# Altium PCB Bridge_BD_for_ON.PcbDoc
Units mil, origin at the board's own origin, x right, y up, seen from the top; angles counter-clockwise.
Board outline 3500 x 4000 mil, 2 copper layers (Top Layer, Bottom Layer); 143 components, 90 nets, 417 pads, 92 vias.
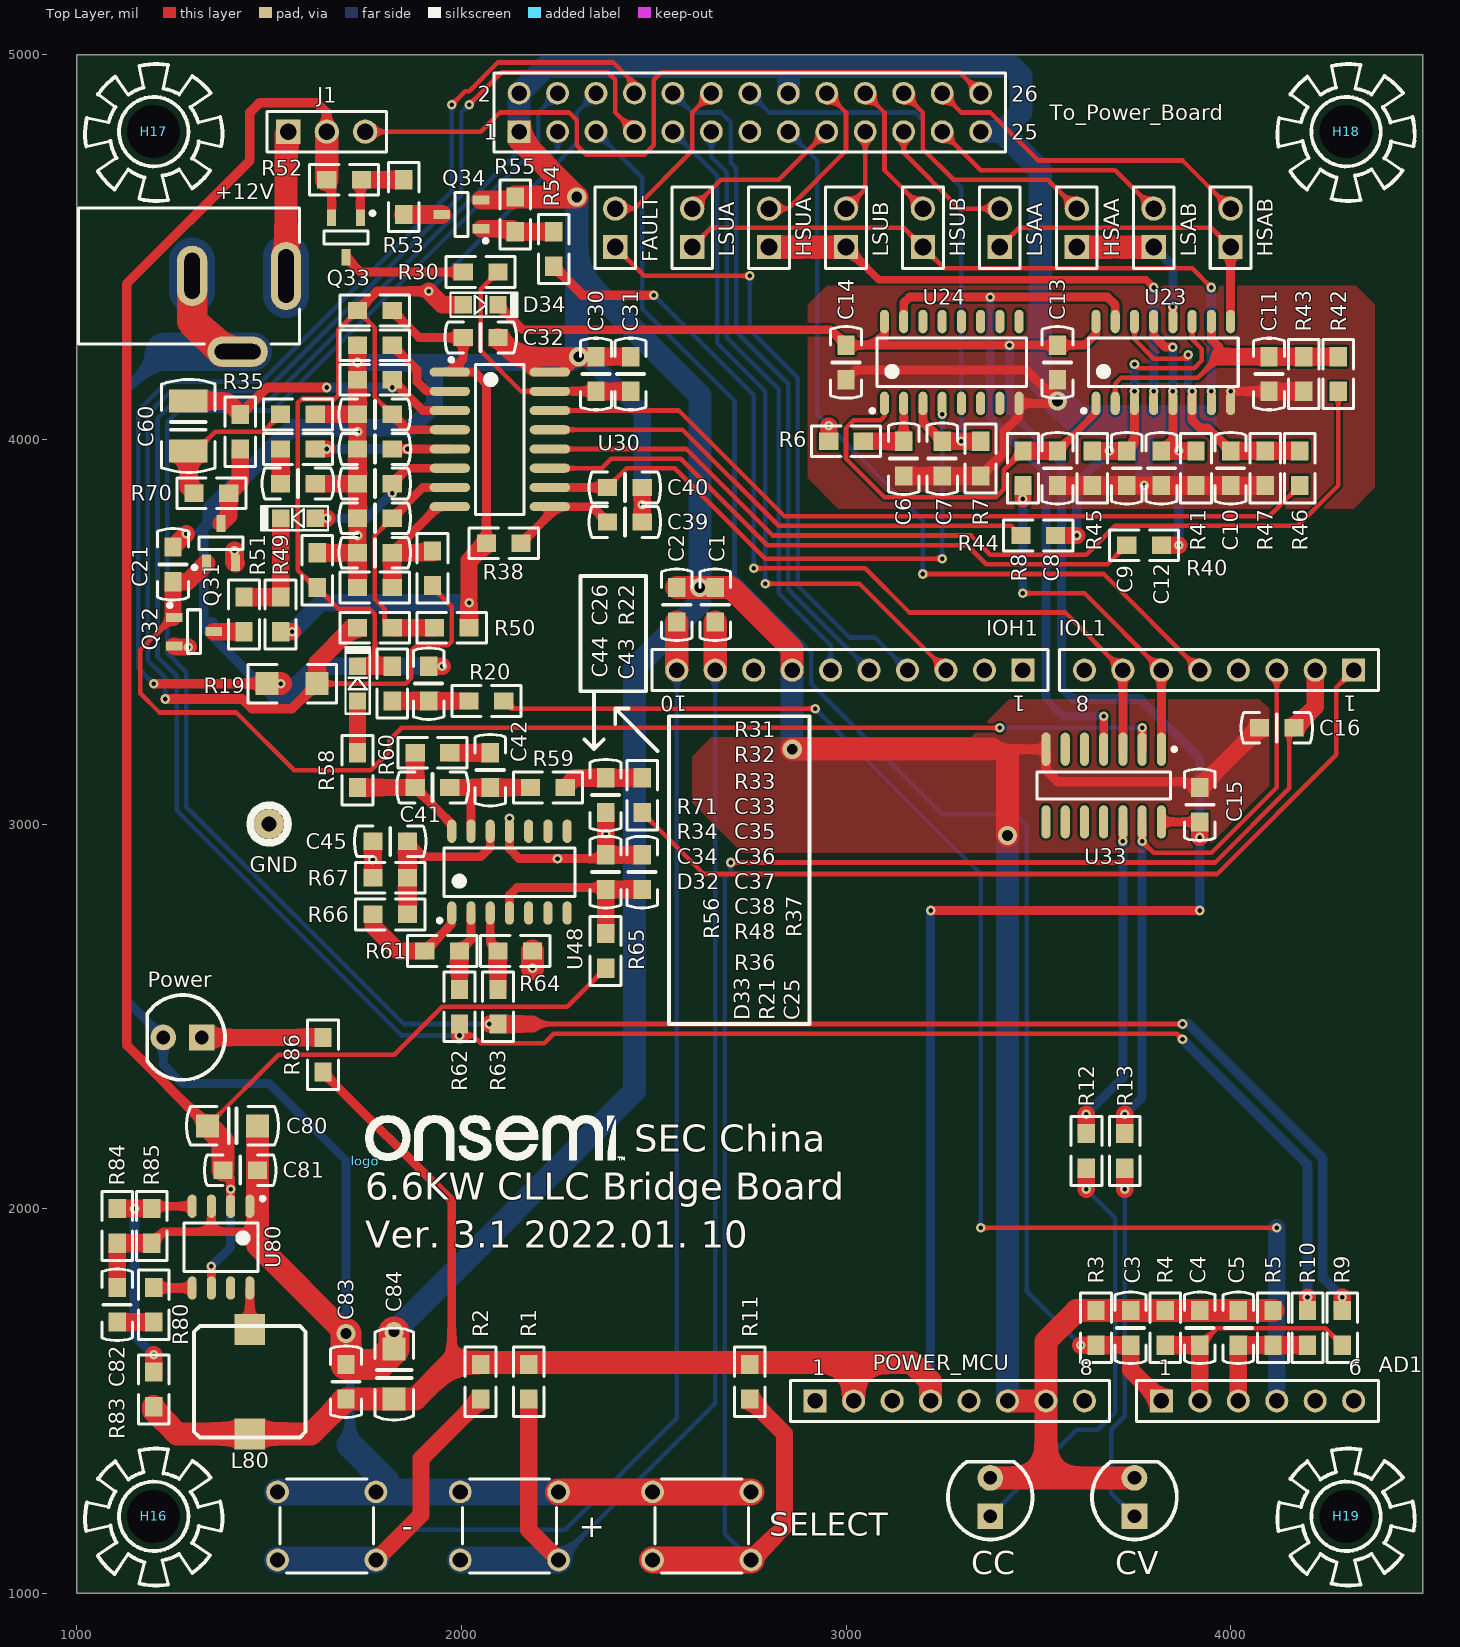
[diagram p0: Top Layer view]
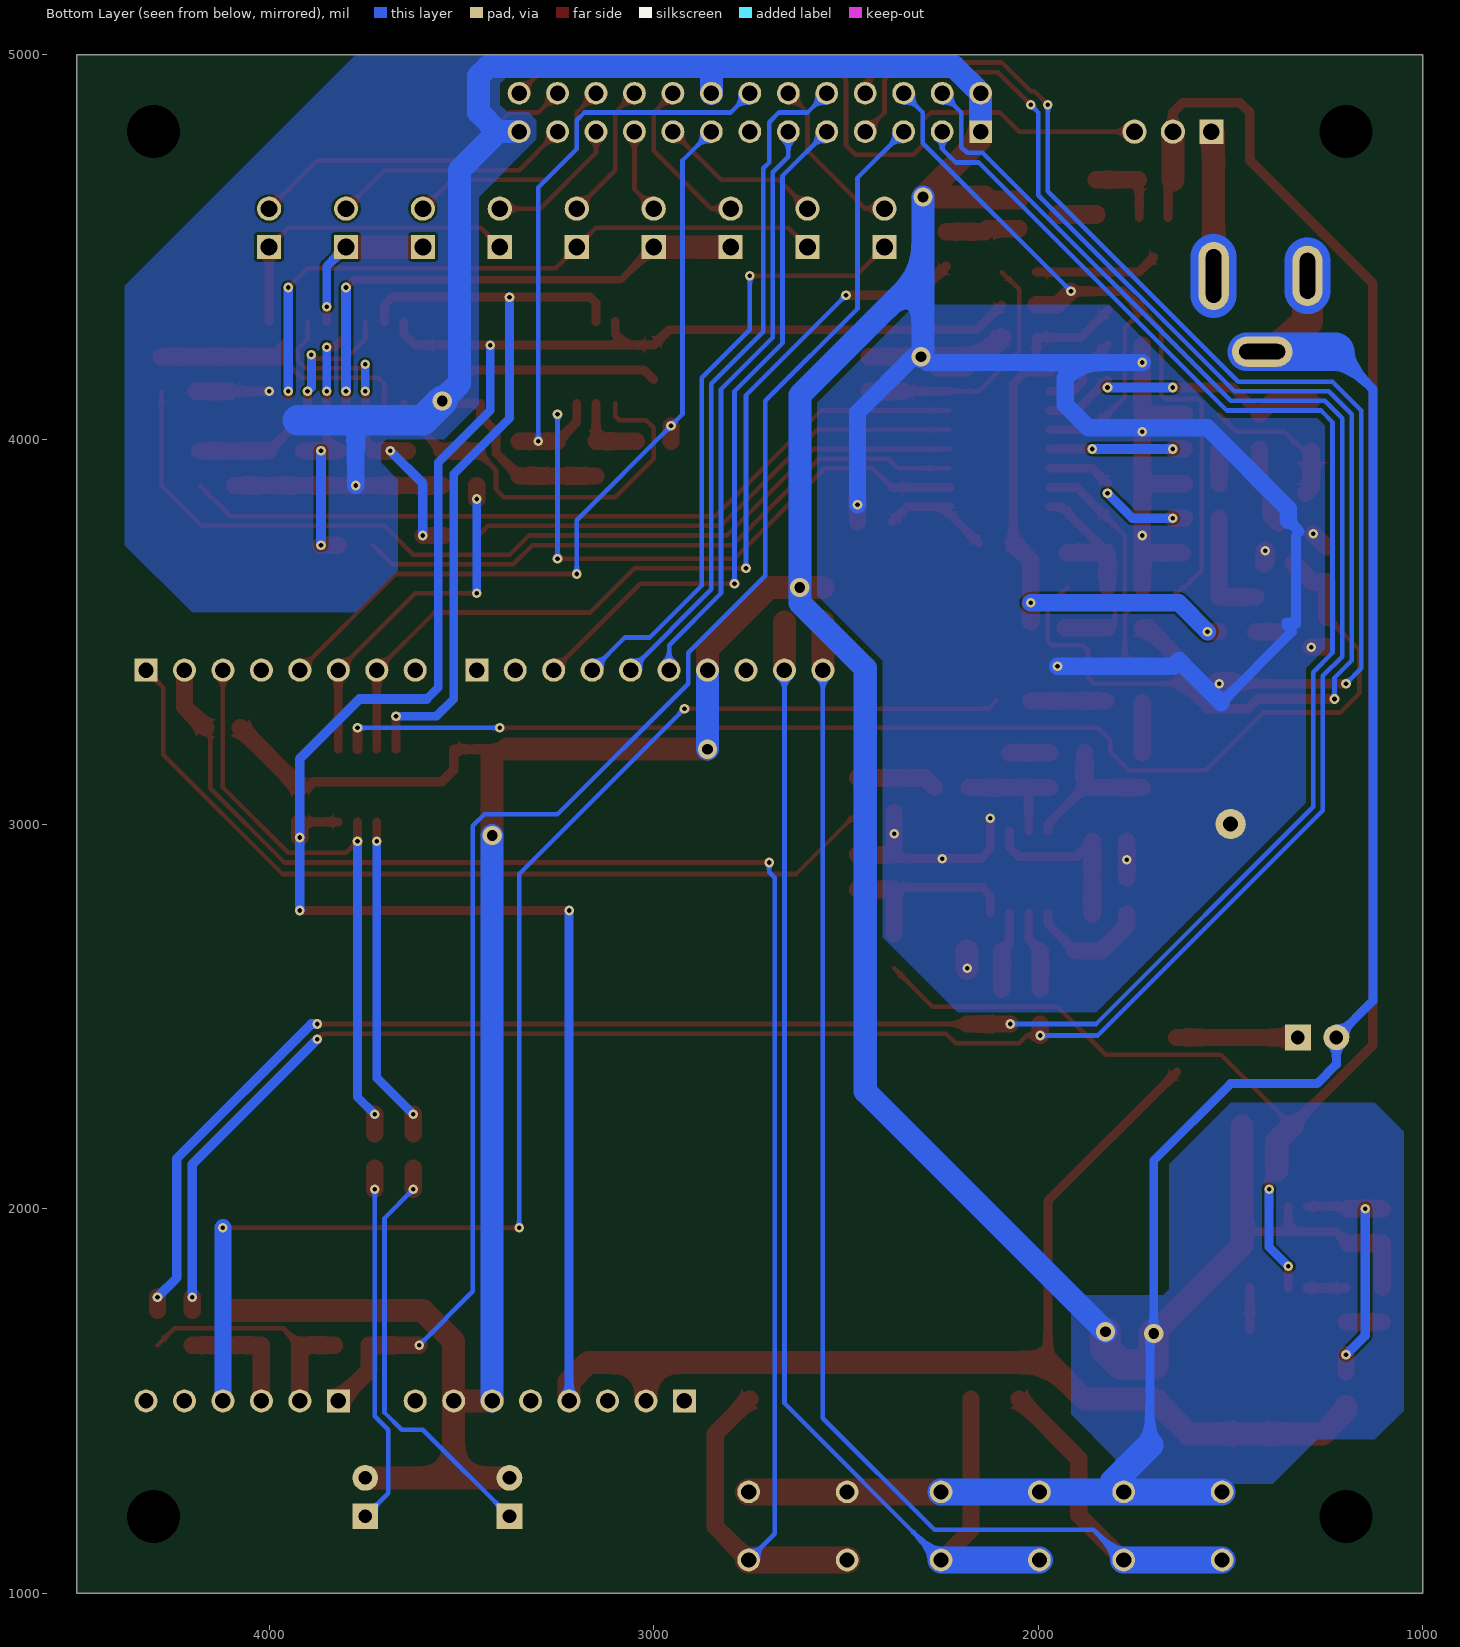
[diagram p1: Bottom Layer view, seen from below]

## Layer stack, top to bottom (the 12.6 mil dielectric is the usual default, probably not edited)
Top Solder: solder mask 0.4, Solder Resist, Dk 3.5
Top Layer: signal copper 1.4
Dielectric 1: dielectric 12.6, FR-4, Dk 4.8
Bottom Layer: signal copper 1.4
Bottom Solder: solder mask 0.4, Solder Resist, Dk 3.5

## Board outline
1000,1000 1000,5000 4500,5000 4500,1000

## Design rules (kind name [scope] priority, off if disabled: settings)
Clearance [All] p1: gap=6 ignorepadtopadclearanceinfootprint=FALSE
PolygonConnect [All] p1: connectstyle=Direct reliefconductorwidth=10 reliefentries=4 polygonreliefangle="90 Angle" airgapwidth=10
RoutingVias [All] p1: holewidth=28 width=50 viastyle="Through Hole" minholewidth=28 minwidth=50 maxholewidth=28 maxwidth=50
SolderMaskExpansion [All] p1: expansion=4
Width [All] p1: maxlimit=200 minlimit=10 preferedwidth=23
30 further rules are at their usual default settings.

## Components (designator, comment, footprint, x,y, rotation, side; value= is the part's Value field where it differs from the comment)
+ "430156050726" 4301x60507x6 2125,1175 r180 top
+12V "PWR2.5" KLD-0202 1004.72,4425 r0 top locked
- "430156050726" 4301x60507x6 1650,1175 r180 top
AD1 "61300611821" 61300611821 4070,1500 r0 top locked
C1 "102" SMT_0805_CM 2660,3570 r270 top
C2 "102" SMT_0805_CM 2560,3570 r270 top
C3 "101" SMT_0805_CM 3740,1690 r270 top
C4 "101" SMT_0805_CM 3920,1690 r270 top
C5 "101" SMT_0805_CM 4020,1690 r270 top
C6 "10" SMT_0805_CM 3150,3950 r90 top
C7 "10" SMT_0805_CM 3250,3950 r90 top
C8 "104" SMT_0805_CM 3550,3925 r90 top
C9 "101" SMT_0805_CM 3730,3925 r90 top
C10 "101" SMT_0805_CM 4000,3925 r90 top
C11 "101" SMT_0805_CM 4100,4170 r90 top
C12 "101" SMT_0805_CM 3820,3925 r90 top
C13 "104" SMT_0805_CM 3550,4200 r90 top
C14 "104" SMT_0805_CM 3000,4200 r90 top
C15 "104" SMT_0805_CM 3920,3050 r270 top
C16 "102" SMT_0805_CM 4120,3250 r0 top
C21 "101" SMT_0805_CM 1250,3675 r270 top
C25 "225" SMT_0805_CM 1915,3365 r270 top
C26 "225" SMT_0805_CM 2375,3075 r90 top
C30 "104" SMT_0805_CM 2350,4170 r270 top
C31 "225" SMT_0805_CM 2440,4170 r270 top
C32 "104" SMT_0805_CM 2050,4265 r180 top
C33 "471" SMT_0805_CM 1775,4065 r0 top
C34 "223" SMT_0805_CM 1575,3885 r180 top
C35 "222" SMT_0805_CM 1775,3975 r0 top
C36 "105" SMT_0805_CM 1775,3885 r0 top
C37 "471" SMT_0805_CM 1775,3795 r0 top
C38 "10" SMT_0805_CM 1775,3705 r0 top
C39 "471" SMT_0805_CM 2425,3785 r180 top
C40 "NC" SMT_0805_CM 2425,3875 r180 top
C41 "104" SMT_0805_CM 1925,3095 r0 top
C42 "NC" SMT_0805_CM 2075,3140 r270 top
C43 "225" SMT_0805_CM 2470,2875 r270 top
C44 "104" SMT_0805_CM 2375,2875 r270 top
C45 "102" SMT_0805_CM 1815,2955 r0 top
C60 "226" SMT_1210 1290,4035 r270 top
C80 "106/25V" SMT_1206_CM 1405,2215 r180 top
C81 "104" SMT_0805_CM 1425,2100 r180 top
C82 "103" SMT_0805_CM 1105,1750 r90 top
C83 "104" SMT_0805_CM 1700,1550 r270 top
C84 "106/25V" SMT_1206_CM 1825,1570 r270 top
CC "Green" "LED 5MM-R" 3375,1250 r90 top
CV "Green" "LED 5MM-R" 3750,1250 r90 top
D32 "BAS16H" SOD-323M 1620,3795 r180 top
D33 "BAS16H" SOD-323M 1730,3320 r90 top
D34 "BAS16H" SOD-323M 2005,4350 r0 top
FAULT "61300211121" 61300211121 2400,4550 r90 top
GND "" test 1500,3000 r0 top
H16 "Comment" HOLE3.5-2 1200,1200 r0 top locked
H17 "Comment" HOLE3.5-2 1200,4800 r0 top locked
H18 "Comment" HOLE3.5-2 4300,4800 r0 top locked
H19 "Comment" HOLE3.5-2 4300,1200 r0 top locked
HSAA "61300211121" 61300211121 3600,4550 r90 top
HSAB "61300211121" 61300211121 4000,4550 r90 top
HSUA "61300211121" 61300211121 2800,4550 r90 top
HSUB "61300211121" 61300211121 3200,4550 r90 top
IOH1 "61301011821" 61301011821 3010,3400 r180 top locked
IOL1 "61300811821" 61300811821 3970,3400 r180 top locked
J1 "61300311121" 61300311121 1650,4800 r0 top
L80 "22uH" INDUCTOR-7*7*3.5 1450,1550 r270 top
logo "Comment" Logo_S 1750,2125 r0 top
LSAA "61300211121" 61300211121 3400,4550 r90 top
LSAB "61300211121" 61300211121 3800,4550 r90 top
LSUA "61300211121" 61300211121 2600,4550 r90 top
LSUB "61300211121" 61300211121 3000,4550 r90 top
Power "Green" "LED 5MM-R" 1275,2445 r180 top locked
POWER_MCU "61300811821" 61300811821 3270,1500 r0 top locked
Q31 "2V7002LT1G" SOT-23-3L 1375,3730 r90 top
Q32 "2V7002LT1G" SOT-23-3L 1305,3500 r0 top
Q33 "NSV40200LT1G" SOT-23-3L 1700,4525 r270 top
Q34 "MMBT3904LT1G" SOT-23-3L 2000,4585 r180 top
R1 "2.2K" SMT_0805_RM 2175,1550 r270 top
R2 "2.2K" SMT_0805_RM 2050,1550 r270 top
R3 "20K" SMT_0805_RM 3650,1690 r90 top
R4 "4.75K" SMT_0805_RM 3830,1690 r90 top
R5 "4.75K" SMT_0805_RM 4110,1690 r90 top
R6 "100" SMT_0805_RM 3000,3995 r0 top
R7 "6.2K" SMT_0805_RM 3350,3950 r270 top
R8 "100" SMT_0805_RM 3460,3925 r90 top
R9 "12.7K" SMT_0805_RM 4290,1690 r90 top
R10 "12.7K" SMT_0805_RM 4200,1690 r90 top
R11 "2.2K" SMT_0805_RM 2750,1550 r270 top
R12 "220" SMT_0805_RM 3625,2150 r270 top
R13 "220" SMT_0805_RM 3725,2150 r270 top
R19 "100" SMT_1206_RM 1560,3365 r0 top
R20 "1K" SMT_0805_RM 2065,3320 r180 top
R21 "120K" SMT_0805_RM 1820,3365 r90 top
R22 "1K" SMT_0805_RM 2470,3075 r90 top
R30 "10" SMT_0805_RM 2050,4435 r0 top
R31 "1M" SMT_0805_RM 1775,4335 r180 top
R32 "51K" SMT_0805_RM 1775,4245 r180 top
R33 "10K" SMT_0805_RM 1775,4155 r180 top
R34 "20K" SMT_0805_RM 1575,3975 r180 top
R35 "24K" SMT_0805_RM 1425,4020 r270 top
R36 "20K" SMT_0805_RM 1775,3510 r180 top
R37 "10K" SMT_0805_RM 1925,3665 r270 top
R38 "82K" SMT_0805_RM 2110,3730 r180 top
R40 "1.2K" SMT_0805_RM 3775,3725 r0 top
R41 "470" SMT_0805_RM 3910,3925 r270 top
R42 "1.2K" SMT_0805_RM 4280,4170 r90 top
R43 "470" SMT_0805_RM 4190,4170 r270 top
R44 "1.2K" SMT_0805_RM 3500,3750 r0 top
R45 "470" SMT_0805_RM 3640,3925 r270 top
R46 "1.2K" SMT_0805_RM 4180,3925 r90 top
R47 "470" SMT_0805_RM 4090,3925 r270 top
R48 "10K" SMT_0805_RM 1775,3615 r180 top
R49 "2.2K" SMT_0805_RM 1530,3545 r90 top
R50 "200K" SMT_0805_RM 1975,3510 r180 top
R51 "2.2K" SMT_0805_RM 1435,3545 r270 top
R52 "2.2K" SMT_0805_RM 1695,4675 r0 top
R53 "2.2K" SMT_0805_RM 1850,4630 r270 top
R54 "4.7K" SMT_0805_RM 2240,4495 r90 top
R55 "2.2K" SMT_0805_RM 2140,4585 r90 top
R56 "68K" SMT_0805_RM 1625,3660 r90 top
R58 "150K" SMT_0805_RM 1730,3140 r270 top
R59 "10K" SMT_0805_RM 2225,3095 r180 top
R60 "NC" SMT_0805_RM 1925,3185 r0 top
R61 "10K" SMT_0805_RM 1950,2670 r0 top
R62 "10K" SMT_0805_RM 1995,2525 r270 top
R63 "10K" SMT_0805_RM 2095,2525 r270 top
R64 "10K" SMT_0805_RM 2140,2670 r180 top
R65 "10" SMT_0805_RM 2375,2670 r90 top
R66 "10K" SMT_0805_RM 1815,2765 r180 top
R67 "30K" SMT_0805_RM 1815,2860 r180 top
R70 "NC" SMT_0805_RM 1350,3860 r0 top
R71 "4.7K" SMT_0805_RM 1575,4065 r0 top
R80 "10K" SMT_0805_RM 1200,1750 r270 top
R83 "4.75K" SMT_0805_RM 1200,1530 r90 top
R84 "NC" SMT_0805_RM 1105,1955 r270 top
R85 "1.5K" SMT_0805_RM 1195,1955 r270 top
R86 "220" SMT_0805_RM 1640,2400 r90 top
SELECT "430156050726" 4301x60507x6 2625,1175 r180 top
To_Power_Board "61302621821" 61302621821 2750,4850 r0 top locked
U23 "NLV74AC157DR2G" SOP16 3825,4200 r90 top
U24 "NLV74AC157DR2G" SOP16 3275,4200 r90 top
U30 "NCV4390" SOP16_NW 2100,4000 r0 top
U33 "NLV74HC04ADR2G" 751A-03_N 3670,3100 r270 top
U48 "NCV33204DR2G" SOP14 2150,2875 r90 top locked
U80 "NCP3170BDR2G" Sop8 1375,1900 r270 top

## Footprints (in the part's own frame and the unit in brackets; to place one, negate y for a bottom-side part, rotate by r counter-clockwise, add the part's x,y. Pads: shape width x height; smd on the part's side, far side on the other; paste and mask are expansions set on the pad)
751A-03_N [mm] "SOIC, 14-Leads, Body 8.7x3.9mm, Pitch 1.27mm, IPC Medium Density"
  oval 2.2x0.6 smd: 1(-2.4,3.81) 2(-2.4,2.54) 3(-2.4,1.27) 4(-2.4,0) 5(-2.4,-1.27) 6(-2.4,-2.54) 7(-2.4,-3.81) 8(2.4,-3.81) 9(2.4,-2.54) 10(2.4,-1.27) 11(2.4,0) 12(2.4,1.27) 13(2.4,2.54) 14(2.4,3.81)
  silkscreen extent -2.52,-4.4 0.9,4.79, body extent -2,-4.38 2,4.38, height 1.75
4301x60507x6 [mm] "6x6mm Tact Switch, THT version"
  round 1.5 hole 1: 1(-3.25,2.25) 2(-3.25,-2.25) 3(3.25,2.25) 4(3.25,-2.25)
  silkscreen extent -3.1,-3.1 3.1,3.1, body extent -3.95,-3.1 3.95,3.1, height 5.05
61300211121 [mm] "Pin Header, pitch 2.54 mm, THT, Vertical, single row, 2p"
  rect 1.6x1.6 hole 1.1: 1(-1.27,0)
  round 1.6 hole 1.1: 2(1.27,0)
  silkscreen extent -2.69,-1.35 2.69,1.35, body extent -2.54,-1.27 2.54,1.27, height 8.57
61300311121 [mm] "Pin Header, pitch 2.54 mm, THT, Vertical, single row, 3p"
  rect 1.6x1.6 hole 1.1: 1(-2.54,0)
  round 1.6 hole 1.1: 2(0,0) 3(2.54,0)
  silkscreen extent -3.96,-1.35 3.96,1.35, body extent -3.81,-1.27 3.81,1.27, height 8.57
61300611821 [mm] "Socket Header, Pitch 2.54 mm, THT, Vertical, single row, 6p"
  rect 1.52x1.52 hole 1.02: 1(-6.35,0)
  round 1.52 hole 1.02: 2(-3.81,0) 3(-1.27,0) 4(1.27,0) 5(3.81,0) 6(6.35,0)
  silkscreen extent -8,-1.35 8,1.35, body extent -7.87,-1.25 7.87,1.25, height 8.55
61300811821 [mm] "Socket Header, Pitch 2.54 mm, THT, Vertical, single row, 8p"
  rect 1.52x1.52 hole 1.02: 1(-8.89,0)
  round 1.52 hole 1.02: 2(-6.35,0) 3(-3.81,0) 4(-1.27,0) 5(1.27,0) 6(3.81,0) 7(6.35,0) 8(8.89,0)
  silkscreen extent -10.54,-1.35 10.54,1.35, body extent -10.41,-1.25 10.41,1.25, height 8.55
61301011821 [mm] "Socket Header, Pitch 2.54 mm, THT, Vertical, single row, 10p"
  rect 1.52x1.52 hole 1.02: 1(-11.43,0)
  round 1.52 hole 1.02: 2(-8.89,0) 3(-6.35,0) 4(-3.81,0) 5(-1.27,0) 6(1.27,0) 7(3.81,0) 8(6.35,0) 9(8.89,0) 10(11.43,0)
  silkscreen extent -13.08,-1.35 13.08,1.35, body extent -12.95,-1.25 12.95,1.25, height 8.55
61302621821 [mm] "Socket Header, Pitch 2.54 mm, THT, Vertical, dual row, 26p"
  rect 1.5x1.5 hole 1.02: 1(-15.24,-1.27)
  round 1.5 hole 1.02: 2(-15.24,1.27) 3(-12.7,-1.27) 4(-12.7,1.27) 5(-10.16,-1.27) 6(-10.16,1.27) 7(-7.62,-1.27) 8(-7.62,1.27) 9(-5.08,-1.27) 10(-5.08,1.27) 11(-2.54,-1.27) 12(-2.54,1.27) 13(0,-1.27) 14(0,1.27) 15(2.54,-1.27) 16(2.54,1.27) 17(5.08,-1.27) 18(5.08,1.27) 19(7.62,-1.27) 20(7.62,1.27) 21(10.16,-1.27) 22(10.16,1.27) 23(12.7,-1.27) 24(12.7,1.27) 25(15.24,-1.27) 26(15.24,1.27)
  silkscreen extent -16.89,-2.62 16.89,2.62, body extent -16.76,-2.54 16.76,2.54, height 8.45
HOLE3.5-2 [mm]
  round 0 hole 3.5 unplated: 1(0,0)
  silkscreen extent -4.53,-4.58 4.54,4.47, body extent -2.49,-2.87 2.51,2.9
INDUCTOR-7*7*3.5 [mil]
  rect 80x80 smd: 1(-135.75,0) 2(135.75,0)
  silkscreen extent -145,-145 145,145, body extent -144,-144 144,144, height 130
KLD-0202 [mm] "DC Power Jack, 2.5mm, KLD Series, PCB Mount"
  oval 2x4.5 hole 1.016 slot 3.556 at 90 deg: 1(13.7,0)
  round 1.5 hole 1: 1A(13.7,-1.25) 1B(13.7,1.25) 2A(7.5,-1) 2B(7.5,1) 3A(9.5,-5) 3B(11.5,-5)
  oval 2x4 hole 1.016 slot 3.048 at 90 deg: 2(7.5,0)
  oval 4x2 hole 1.016 slot 3.048 at 0 deg: 3(10.5,-5)
  silkscreen extent 0,-4.5 14.6,4.5
"LED 5MM-R" [mm] "红色5mm直插LED"
  rect 1.7x1.7 hole 0.9: 1(-1.27,0)
  round 1.7 hole 0.9: 2(1.27,0)
  silkscreen extent -2.8,-2.8 2.33,2.8, body extent -2.85,-2.85 2.45,2.85, height 8.75
Logo_S [mil]
  silkscreen extent 0,1 675,118
SMT_0805_CM [mil]
  rect 50x45 smd: 1(-45,0) 2(45,0)
  silkscreen extent -93,-40 93,40, body extent -39,-24 39,24, height 26
SMT_0805_RM [mil]
  rect 50x45 smd: 1(-45,0) 2(45,0)
  silkscreen extent -90,-40 90,40, body extent -39,-25 39,25, height 22
SMT_1206_CM [mil]
  rect 60x60 smd: 1(-65,0) 2(65,0)
  silkscreen extent -120,-50 120,50, body extent -63,-31 63,31, height 30
SMT_1206_RM [mil]
  rect 60x60 smd: 1(-65,0) 2(65,0)
  silkscreen extent -115,-50 115,50, body extent -63,-31 63,31, height 24
SMT_1210 [mil]
  rect 60x100 smd: 1(-65,0) 2(65,0)
  silkscreen extent -121,-70 121,70, body extent -63,-31 63,31, height 30
SOD-323M [mil]
  rect 45x45 smd: 1(0,0) 2(90,0)
  silkscreen extent -33,-31 140,31, body extent 2,-24 100,26, height 35
Sop8 [mm]
  oval 1.55x0.6 smd: 1(-2.7,1.905) 2(-2.7,0.635) 3(-2.7,-0.635) 4(-2.7,-1.905) 5(2.7,-1.905) 6(2.7,-0.635) 7(2.7,0.635) 8(2.7,1.905)
  silkscreen extent -3.32,-2.45 1.6,2.88, body extent -3,-2.45 3,2.45, height 1.6
SOP14 [mm]
  oval 1.55x0.6 smd: 1(-2.7,4.445) 2(-2.7,3.175) 3(-2.7,1.905) 4(-2.7,0.635) 5(-2.7,-0.635) 6(-2.7,-1.905) 7(-2.7,-3.175) 8(2.7,-3.175) 9(2.7,-1.905) 10(2.7,-0.635) 11(2.7,0.635) 12(2.7,1.905) 13(2.7,3.175) 14(2.7,4.445)
  silkscreen extent -3.32,-3.68 1.6,5.37, body extent -3,-5 3,5, height 1.6
SOP16 [mm]
  oval 1.55x0.6 smd: 1(-2.7,4.445) 2(-2.7,3.175) 3(-2.7,1.905) 4(-2.7,0.635) 5(-2.7,-0.635) 6(-2.7,-1.905) 7(-2.7,-3.175) 8(-2.7,-4.445) 9(2.7,-4.445) 10(2.7,-3.175) 11(2.7,-1.905) 12(2.7,-0.635) 13(2.7,0.635) 14(2.7,1.905) 15(2.7,3.175) 16(2.7,4.445)
  silkscreen extent -3.32,-4.95 1.6,5.37, body extent -3,-5 3,5, height 1.6
SOP16_NW [mil]
  oval 105x23.62 smd: 1(-130,175) 2(-130,125) 3(-130,75) 4(-130,25) 5(-130,-25) 6(-130,-75) 7(-130,-125) 8(-130,-175) 9(130,-175) 10(130,-125) 11(130,-75) 12(130,-25) 13(130,25) 14(130,75) 15(130,125) 16(130,175)
  silkscreen extent -131,-195 63,212, body extent -118,-197 118,197, height 63
SOT-23-3L [mm]
  rect 1.1x0.6 smd: 1(-1.3,0.95) 2(-1.3,-0.95) 3(1.3,0)
  silkscreen extent -1.72,-1.45 0.43,1.87, body extent -1.4,-1.45 1.4,1.45, height 1.2
test [mm]
  round 2 hole 1: 1(0,0)
  silkscreen extent -1.25,-1.25 1.25,1.25, body extent -1.27,-1.32 1.27,1.32, height 4.36

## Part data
+ - SELECT: "WS-TATV THT Tact Switch 6x6mm, height 5mm, 260gf", Operating Temperature="-40 to +85degC", Rated Current=50mA, Rated Voltage=12VDC
+12V: "Low Voltage Power Supply Connector"
AD1: "WR-PHD Socket Header, THT, pitch 2.54mm, Single Row, Vertical, 6pin", Contact Resistance=20mOhm, Operating Temperature="-40 to +125degC", Rated Current=3A, Withstanding Voltage=500VAC, Working Voltage=250VAC
C1 C2 C3 C4 C5 C6 C7 C8 C9 C10 C11 C12 C13 C14 C15 C16 C21 C25 C26 C30 C31 C32 C33 C34 C35 C36 C37 C38 C39 C40 C43 C44 C45 C81 C83: library part CAP_0805
C41 C42 C60 C80 C82 C84: library part "CAP NP"
CC CV Power: library part LED
D32 D33 D34: library part DIODE
FAULT HSAA HSAB HSUA HSUB LSAA LSAB LSUA LSUB: "WR-PHD Pin Header, THT, pitch 2.54mm, Single Row, Vertical, 2pin", Contact Resistance=20mOhm, Operating Temperature="-40 to +105degC", Rated Current=3A, Withstanding Voltage=500VAC, Working Voltage=250VAC
GND: library part Plug, "Plug"
IOH1: "WR-PHD Socket Header, THT, pitch 2.54mm, Single Row, Vertical, 10pin", Contact Resistance=20mOhm, Operating Temperature="-40 to +125degC", Rated Current=3A, Withstanding Voltage=500VAC, Working Voltage=250VAC
IOL1 POWER_MCU: "WR-PHD Socket Header, THT, pitch 2.54mm, Single Row, Vertical, 8pin", Contact Resistance=20mOhm, Operating Temperature="-40 to +125degC", Rated Current=3A, Withstanding Voltage=500VAC, Working Voltage=250VAC
J1: "WR-PHD Pin Header, THT, pitch 2.54mm, Single Row, Vertical, 3pin", Contact Resistance=20mOhm, Operating Temperature="-40 to +105degC", Rated Current=3A, Withstanding Voltage=500VAC, Working Voltage=250VAC
L80: library part "INDUCTOR IRON"
Q31 Q32: library part "MOSFET N", "NTPF082N65S3F"
Q33: library part "PNP BCE"
Q34: library part "NPN BCE"
R1 R2 R3 R4 R5 R7 R9 R10 R11 R12 R13 R19 R31 R32 R33 R34 R35 R38 R40 R41 R42 R43 R44 R45 R46 R47 R48 R49 R50 R51 R52 R55 R56 R58 R64 R67 R70 R71 R80 R83 R84 R85 R86: library part R
R6 R8 R20 R21 R22 R30 R36 R37 R53 R54 R59 R60 R61 R62 R63 R65 R66: library part R_0805
To_Power_Board: "WR-PHD Socket Header, THT, pitch 2.54mm, Dual Row, Vertical, 26pin", Contact Resistance=20mOhm, Operating Temperature="-40 to +125degC", Rated Current=3A, Withstanding Voltage=500VAC, Working Voltage=250VAC
U23 U24: library part 74HC157
U30: library part FAN7688
U33: library part MC74HC04ADR2, "Hex Inverter"
U48: library part LM324
U80: library part NCP3170

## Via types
v1: diameter 25, hole 12, Top Layer to Bottom Layer, 84 vias
v2: diameter 50, hole 28, Top Layer to Bottom Layer, 8 vias

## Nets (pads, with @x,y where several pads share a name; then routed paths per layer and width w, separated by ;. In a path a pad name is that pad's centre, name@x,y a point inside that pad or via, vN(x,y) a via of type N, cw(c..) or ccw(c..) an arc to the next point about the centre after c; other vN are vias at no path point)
3.3V: C13.2 C14.2 C15.2 C83.2 C84.2 D34.2 L80.2 POWER_MCU.2 POWER_MCU.4 R1.1 R2.1 R11.1 R83.1 R86.1 U23.16 U24.16 U33.14 | length 8805.3
  Top Layer w23: R86.1 1975,2020 1975,1600 ; D34.2 2160,4285 2960,4285 C14.2 3070,4245 ; U24.16 3100,4275 3070,4245 ; v1(3220,2775) v1(3920,2775) ; U23.16 3650,4275 3620,4245 C13.2 v1(3425,4245) 3070,4245 ; U33.14 3919.49,3005.51 C15.2
  Top Layer w45: v1(3920,2965) C15.2
  Top Layer w60: R83.1 1200,1475 1260.75,1414.25 L80.2 1609.25,1414.25 C83.2 C84.2 1880,1505 1975,1600 2750,1600 3020,1600 ; POWER_MCU.2 3020,1600 ; POWER_MCU.4 3220,1550 3170,1600 3020,1600
  Bottom Layer w23: POWER_MCU.4 v1(3220,2775) ; v1(3425,4245) 3425,4075 3560,3940 3560,3355 3590,3325
  Bottom Layer w25: 3590,3325 3765,3325 3920,3170 v1(3920,2965) v1(3920,2775)
+5V: C32.2 R31.1 R38.2 R49.1 R50.1 U30.1 | length 1585.6
  Top Layer w23: R31.1 1890,4265 C32.2 2005,4210 U30.1 2035,4175 2065,4145 R38.2
  Top Layer w45: R49.1 v1(1560,3500) ; R50.1@2020,3525 v1(2020,3575) 2020,3685 R38.2
  Bottom Layer w45: v1(1560,3500) 1635,3575 v1(2020,3575)
+12V: C80.2 C81.2 J1.2 Q33.2 R52.1 R65.1 U80.2 U80.6 | length 5066.1
  Top Layer w12: C80.2@1342.5,2217.5 1525,2400 1825,2400 1950,2525 2275,2525 R65.1
  Top Layer w23: U80.6 v1(1350,1850) ; C81.2 1400,2080 v1(1400,2050) U80.2 ; R52.1 1662.6,4662.4 Q33.2
  Top Layer w25: C80.2 1130,2425 1130,4405 1450,4725 1450,4850 1475,4875 1625,4875 1650,4850 J1.2
  Top Layer w60: C80.2 1380,2175 C81.2 ; R52.1 J1.2
  Bottom Layer w23: v1(1350,1850) 1400,1900 v1(1400,2050)
GND: +12V.2 +12V.2A +12V.2B +12V.3 +12V.3A +12V.3B +.2 +.4 -.2 -.4 C1.1 C2.1 C3.1 C4.1 C5.1 C6.1 C7.1 C8.1 C9.1 C10.1 C11.1 C12.1 C13.1 C14.1 C15.1 C16.1 C21.1 C25.1 C26.1 C30.1 C31.1 C32.1 C33.1 C34.1 C35.1 C36.1 C37.1 C38.1 C39.1 C40.1 C43.1 C44.1 C45.1 C80.1 C81.1 C82.2 C83.1 C84.1 CC.2 CV.2 GND.1 IOH1.7 Power.2 POWER_MCU.6 POWER_MCU.7 Q31.2 Q32.2 Q34.2 R3.2 R4.2 R5.2 R7.2 R19.1 R32.2 R33.2 R41.2 R43.2 R45.2 R47.2 R48.2 R55.2 R56.2 R64.1 R67.2 R71.2 R84.2 R85.2 SELECT.2 SELECT.4 To_Power_Board.1 To_Power_Board.2 To_Power_Board.8 To_Power_Board.16 To_Power_Board.25 U23.8 U24.8 U30.16 U33.7 U48.11 U80.1 U80.3 | length 29059.5
  Top Layer w12: v1(1975,4870) 2010,4905 2020,4905 2095,4980 2395,4980 2450,4925 To_Power_Board.8
  Top Layer w23: R85.2 1225,1940 1350,1940 ; U80.3 1350,1940 ; 1470,1970 1440,1940 1350,1940 ; 1470,1977.52 1475.47,1983.68 ; v1(2125,3015) U48.11 2125,2935 2150,2910 v1(2250,2910) 2365,2910 C44.1 ; 2145,4215 2185,4175 U30.16 2265,4175 v2(2305,4215) ; C14.1 3025,4180 3470,4180 v2(3550,4100) 3543.7,4093.7 U24.8 3450,4060 3410,4020 3410,3965 R7.2
  Top Layer w25: v1(1200,3365) R19.1 ; 3379.49,3194.49 U33.7 3520,3140 3550,3110 3885,3110 3900,3095 C15.1 ; v1(4000,4125) C11.1
  Top Layer w45: C82.2 R84.2 R85.2 ; C21.1 v1(1285,3755) ; Q32.2 1256.42,3460 v1(1290,3460) ; C34.1 C36.1 ; R71.2 C33.1 ; R56.2 C38.1 ; R48.2 C38.1 ; R32.2 v1(1730,4200) R33.2 C33.1 ; R67.2 v1(1770,2907.5) C45.1 ; C25.1 v1(1950,3410) ; C30.1 C31.1 ; C26.1 v1(2375,2975) C44.1 C43.1 ; C39.1 v1(2470,3830) C40.1 ; C6.1 C7.1 R7.2 ; C8.1 R45.2 C9.1 v1(3775,3880) C12.1 R41.2 C10.1 R47.2 ; C15.1 C16.1 ; C11.1 R43.2 ; C38.1 v1(1730,3750) C37.1 C36.1 ; C36.1 C35.1 v1(1730,4020) C33.1
  Top Layer w50: v1(1410,3710) 1410,3681.22 Q31.2 ; Q34.2 2132.4,4622.4 R55.2 ; C32.1 2145,4215 v2(2305,4215) C30.1
  Top Layer w60: 1470,1970 1470,1905 v2(1700,1675) ; 1470,1977.52 C81.1 C80.1 ; R19.1 v1(1530,3365) ; R55.2 v2(2300,4630) 2150,4780 To_Power_Board.1 ; v1(2185,2625) R64.1 ; C2.1 v2(2620,3615) C1.1 2700,3615 2860,3455 IOH1.7 ; v2(2860,3194.49) 3379.49,3194.49 ; CC.2 3520,1300 ; POWER_MCU.6 POWER_MCU.7 ; v2(3420,2970) 3420,3175 ; CV.2 3520,1300 ; R5.2 C5.1 C4.1 R4.2 C3.1 R3.2 3600,1735 3520,1655 POWER_MCU.7 ; 3520,1300 POWER_MCU.7
  Top Layer w70: +.2 SELECT.4 SELECT.2
  Top Layer w80: +12V.2A 1300,4306.89 +12V.3A ; v2(1700,1675) C83.1 1785,1595 C84.1 v2(1825,1680)
  Bottom Layer w12: v1(1200,3365) 1160,3405 1160,4075 1235,4150 1480,4150 1975,4645 v1(1975,4870)
  Bottom Layer w23: 1228.15,4228.15 1130,4130 1130,2540 Power.2 1225,2375 1275,2325 1500,2325 1700,2125 v2(1700,1675) 1710,1665 1710,1385
  Bottom Layer w25: 1350,3790 1320,3760 1330,3750 1330,3520 1335,3525 1355,3525 1355,3515 1340,3500 1525,3315
  Bottom Layer w45: 1350,3790 1350,3820 1560,4030 1870,4030 1930,4090 1930,4160 1890,4200 ; 1525,3315 1635,3425 1650,3410 v1(1950,3410) ; v1(1730,4200) 1890,4200 ; v1(2470,3830) 2470,4070 2325,4215 v2(2305,4215) 2290,4200 1890,4200 ; v1(3775,3880) 3775,4050
  Bottom Layer w60: v2(1825,1680) 2450,2305 2450,3405 2620,3575 v2(2620,3615) 2620,4115 2300,4435 ; To_Power_Board.1 To_Power_Board.2 2219.53,4969.53 2845.47,4969.53 2850,4965 ; v2(2300,4630) 2300,4435 ; v2(2305,4215) 2300,4220 2300,4435 ; To_Power_Board.16 2850,4965 ; v2(2860,3194.49) IOH1.7 ; To_Power_Board.25 3405,4800 ; POWER_MCU.6 v2(3420,2970) ; v2(3550,4100) 3505,4145 3505,4700 3405,4800 ; 2850,4965 2854.53,4969.53 3430.47,4969.53 3455,4945 3455,4850 3405,4800
  Bottom Layer w70: -.4 -.2 1831.42,1263.58 1923.58,1263.58 +.4 +.2 ; 1710,1385 1804.68,1290.32
  Bottom Layer w80: v2(3550,4100) 3600,4050 3775,4050 3925,4050
  Bottom Layer w100: 1228.15,4228.15 +12V.3A +12V.3 +12V.3B
  Bottom Layer w120: +12V.2A +12V.2 +12V.2B
Net+12V_1: +12V.1 +12V.1A +12V.1B J1.1 | length 475.9
  Top Layer w60: +12V.1 +12V.1B 1544.09,4794.09 J1.1
  Bottom Layer w120: +12V.1A +12V.1 +12V.1B
Net+_1: +.1 +.3 C1.2 IOH1.9 R1.2 | length 3314
  Top Layer w45: R1.2 2175,1164.37 +.1
  Top Layer w60: IOH1.9 C1.2
  Bottom Layer w12: +.1 2660,1493.46 IOH1.9
  Bottom Layer w70: +.3 +.1
Net-_1: -.1 -.3 C2.2 IOH1.10 R2.2 | length 3791.9
  Top Layer w45: -.1 1895,1203.46 1895,1350 R2.2
  Top Layer w60: IOH1.10 C2.2
  Bottom Layer w12: -.1 1856.54,1165 2270,1165 2560,1455 IOH1.10
  Bottom Layer w70: -.3 -.1
NetAD1_1: AD1.1 C3.2 R3.1 To_Power_Board.5 | length 4096.3
  Top Layer w45: v1(3610,1645) R3.1 C3.2 3740,1580 AD1.1
  Bottom Layer w12: To_Power_Board.5 2470,4680 2470,4340 2710,4100 2710,3645 2910,3445 2910,3365 3250,3025 3440,3025 3470,2995 3470,1785 v1(3610,1645)
NetAD1_2: AD1.2 C4.2 R4.1 R9.1 | length 641.5
  Top Layer w12: C4.2 3964,1689 4246,1689 R9.1
  Top Layer w45: R4.1 C4.2 AD1.2
NetAD1_3: AD1.3 C5.2 R5.1 R10.1 | length 325
  Top Layer w45: AD1.3 C5.2 R5.1 R10.1
NetAD1_4: AD1.4 R20.1 | length 3566.4
  Top Layer w12: R20.1 2130,3300 v1(2920,3300) ; v1(3350,1950) v1(4120,1950)
  Bottom Layer w12: v1(2920,3300) 3350,2870 v1(3350,1950)
  Bottom Layer w45: AD1.4 v1(4120,1950)
NetC6_2: C6.2 R6.2 U24.2 | length 203.7
  Top Layer w23: C6.2 U24.2
  Top Layer w45: R6.2 C6.2
NetC7_2: C7.2 R7.1 To_Power_Board.14 U24.3 | length 1574.8
  Top Layer w23: U24.3 3200,4045 C7.2
  Top Layer w45: C7.2 v1(3300,3995) R7.1
  Bottom Layer w12: To_Power_Board.14 2800,4850 3180,4850 3200,4830 3200,4755 3300,4655 v1(3300,3995)
NetC8_2: C8.2 R8.2 U23.1 U24.1 | length 1061.7
  Top Layer w12: U24.1 3100,4060 3090,4050 3020,4050 3000,4030 3000,3950 3100,3850 3390,3850 3410,3870 3410,3920 R8.2
  Top Layer w19: C8.2 3650,4070 U23.1
  Top Layer w45: R8.2 C8.2
NetC9_2: C9.2 R44.2 R45.1 U23.3 U23.11 | length 932.6
  Top Layer w12: v1(3750,4195) 3760,4185 3905,4185 3925,4205 3925,4235 3900,4260 U23.11
  Top Layer w23: C9.2 3750,3990 U23.3 v1(3750,4125)
  Top Layer w45: R44.2 v1(3600,3750) ; R45.1 v1(3685,3970) C9.2
  Bottom Layer w23: v1(3750,4125) v1(3750,4195)
  Bottom Layer w25: v1(3600,3750) 3600,3885 v1(3685,3970)
NetC10_2: C10.2 R46.2 R47.1 U23.6 U23.14 | length 704.3
  Top Layer w12: U23.14 3750,4260 3800,4210 3890,4210 v1(3890,4220)
  Top Layer w23: v1(3900,4125) U23.6 3900,4050 3920,4030 3940,4030 C10.2
  Top Layer w45: C10.2 R47.1 R46.2
  Bottom Layer w23: v1(3890,4220) 3890,4135 v1(3900,4125)
NetC11_2: C11.2 R42.2 R43.1 U23.2 U23.10 | length 759.9
  Top Layer w12: U23.2 3700,4145 3715,4160 3915,4160 3970,4215
  Top Layer w23: U23.10 3950,4260 3970,4240 3970,4215
  Top Layer w45: 3970,4215 C11.2 R43.1 R42.2
NetC12_2: C12.2 R40.2 R41.1 U23.5 U23.13 | length 761.2
  Top Layer w23: U23.13 3800,4270 3830,4240 v1(3850,4240) ; C12.2 3850,4000 U23.5 v1(3850,4125)
  Top Layer w45: R40.2 v1(3865,3725) ; C12.2 v1(3865,3970) R41.1
  Bottom Layer w23: v1(3850,4125) v1(3850,4240)
  Bottom Layer w25: v1(3865,3725) v1(3865,3970)
NetC16_2: C16.2 IOL1.2 R11.2 SELECT.1 SELECT.3 | length 4463.5
  Top Layer w12: v1(2700,2900) 3960,2900 4152.5,3092.5 4152.5,3237.5 C16.2
  Top Layer w45: R11.2 2840,1415 2840,1173.46 SELECT.1 ; C16.2 4220,3305 IOL1.2
  Top Layer w70: SELECT.3 SELECT.1
  Bottom Layer w12: v1(2700,2900) 2700,2875 2685,2860 2685,1154.37 SELECT.1
NetC21_2: C21.2 Q31.1 Q32.1 U33.2 | length 3243
  Top Layer w12: Q32.1 1250,3537.4 1165,3452.4 1165,3340 1215,3290 1415,3290 1565,3140 1764.5,3140 1812.5,3188 1812.5,3217.5 1845,3250 v1(3400,3250)
  Top Layer w25: U33.2 v1(3770,3250)
  Top Layer w45: Q32.1@1250,3537.4 C21.2 1288.78,3630 Q31.1
  Bottom Layer w12: v1(3400,3250) v1(3770,3250)
NetC25_2: C25.2 R20.2 R21.1 | length 195
  Top Layer w45: R21.1@1825,3320 C25.2 R20.2
NetC26_2: C26.2 R22.2 R59.1 | length 210.4
  Top Layer w45: R59.1 2295,3120 C26.2 R22.2
NetC30_2: C30.2 C31.2 R30.2 U30.15 | length 657.1
  Top Layer w12: R30.2 2050,4390 2050,4230 2155,4125 U30.15
  Top Layer w23: U30.15 C30.2
  Top Layer w45: C30.2 C31.2
NetC33_2: C33.2 D33.2 D34.1 R21.2 R31.2 R56.1 To_Power_Board.6 U30.4 | length 2740.9
  Top Layer w12: 1775,3410 1775,3545 1760,3560 1680,3560 R56.1 1620,3615 1575,3660 1575,4095 1585,4105 1670,4105 1680,4115 1680,4285 R31.2 1775,4290 1775,4110 C33.2
  Top Layer w23: C33.2 1860,4025 U30.4
  Top Layer w25: R31.2 1780,4385 v1(1915,4385)
  Top Layer w45: D33.2 1775,3410 R21.2 ; v1(1915,4385) 1950,4350 D34.1
  Bottom Layer w12: v1(1915,4385) 2300,4770 2300,4850 To_Power_Board.6
NetC34_2: C34.2 R34.2 | length 90
  Top Layer w45: C34.2 R34.2
NetC35_2: C35.2 R34.1 U30.5 | length 390
  Top Layer w23: C35.2 v1(1860,3975) U30.5
  Top Layer w45: R34.1 v1(1650,3975)
  Bottom Layer w25: v1(1650,3975) v1(1860,3975)
NetC36_2: C36.2 D32.1 U30.6 | length 393.5
  Top Layer w23: C36.2 1860,3925 U30.6
  Top Layer w45: D32.1 v1(1650,3795)
  Bottom Layer w25: v1(1650,3795) 1755,3795 v1(1820,3860)
NetC37_2: C37.2 R36.1 R50.2 U30.7 | length 615.4
  Top Layer w12: R36.1 1800,3530 1800,3560 1775,3585 1775,3750 C37.2
  Top Layer w23: C37.2 1900,3875 U30.7
  Top Layer w45: R36.1 R50.2
NetC38_2: C38.2 R37.1 R48.1 U30.8 | length 394.7
  Top Layer w23: C38.2 1940,3825 U30.8
  Top Layer w45: R48.1 C38.2 R37.1@1925,3705
NetC39_2: C39.2 R38.1 U30.9 | length 315.1
  Top Layer w23: R38.1 U30.9@2240,3815 ; C39.2 2340,3825 U30.9@2250,3825 ; U30.9@2240,3815 U30.9@2250,3825 ; U30.9@2240,3815 U30.9 U30.9@2250,3825
NetC40_2: C40.2 U24.4 U30.10 | length 1513.1
  Top Layer w12: C40.2 2430,3925 2555,3925 2790,3690 v1(3250,3690)
  Top Layer w23: U30.10 C40.2
  Bottom Layer w12: v1(3250,3690) v1(3250,4065)
NetC41_1: C41.1 R58.2 R60.1 U48.14 | length 393.1
  Top Layer w23: C41.1 1975,3000 U48.14
  Top Layer w45: R58.2 C41.1 R60.1
NetC41_2: C41.2 C42.2 R59.2 U48.13 | length 323.7
  Top Layer w23: U48.13 2025,3095
  Top Layer w45: C41.2 2025,3095 C42.2 R59.2
NetC42_1: C42.1 R60.2 | length 105
  Top Layer w45: R60.2 C42.1
NetC43_2: C43.2 C44.2 R65.2 U48.4 | length 509.6
  Top Layer w23: U48.4 2125,2815 2145,2835 C44.2@2370,2835
  Top Layer w45: R65.2 C44.2 C43.2
NetC45_2: C45.2 R66.1 R67.1 U48.12 | length 473.2
  Top Layer w23: C45.2 1900,2915 2050,2915 2075,2940 U48.12
  Top Layer w45: R66.1 R67.1 C45.2
NetC60_1: C60.1 R33.1 R35.1 U30.3 | length 756.6
  Top Layer w23: R33.1 1900,4075 U30.3
  Top Layer w25: R35.1 1495,4135 v1(1650,4135)
  Top Layer w45: C60.1 1390,4100 R35.1
  Bottom Layer w25: v1(1650,4135) v1(1820,4135)
NetC60_2: C60.2 R70.1 R71.1 | length 395.6
  Top Layer w12: C60.2 1310,3970 1360,4020 1485,4020 R71.1
  Top Layer w45: C60.2 1290,3875 R70.1
NetC82_1: C82.1 R80.2 | length 95
  Top Layer w45: C82.1 R80.2
NetCC_1: CC.1 R12.2 | length 1102.9
  Top Layer w45: v1(3625,2050) R12.2
  Bottom Layer w12: CC.1 3600,1425 3655,1425 3700,1470 3700,1975 v1(3625,2050)
NetCV_1: CV.1 R13.2 | length 944.4
  Top Layer w45: v1(3725,2050) R13.2
  Bottom Layer w12: v1(3725,2050) 3725,1460 3690,1425 3690,1260 CV.1
NetD32_2: D32.2 R49.2 R51.1 | length 300
  Top Layer w45: R51.1 R49.2 D32.2
NetD33_1: D33.1 R58.1 | length 130
  Top Layer w45: R58.1 D33.1@1730,3315
NetFAULT_1: FAULT.1 IOH1.4 | length 1614
  Top Layer w12: FAULT.1 2475,4425 v1(2750,4425)
  Bottom Layer w12: v1(2750,4425) 2750,4285 2875,4160 2875,3620 3010,3485 3075,3485 IOH1.4
NetFAULT_2: FAULT.2 To_Power_Board.12 | length 432.8
  Top Layer w12: FAULT.2 2450,4600 2600,4750 2600,4850 To_Power_Board.12
NetHSAA_1: HSAA.1 LSAB.1 U23.12 | length 414.4
  Top Layer w23: U23.12 v1(3850,4345)
  Top Layer w60: HSAA.1 LSAB.1
  Bottom Layer w23: LSAB.1 3850,4450 v1(3850,4345)
NetHSAA_2: HSAA.2 To_Power_Board.22 | length 629.9
  Top Layer w12: To_Power_Board.22 3200,4850 3200,4755 3280,4675 3525,4675 HSAA.2
NetHSAB_1: HSAB.1 LSAA.1 U23.9 | length 835.1
  Top Layer w12: LSAA.1 3450,4550 3950,4550 HSAB.1
  Top Layer w23: U23.9 HSAB.1
NetHSAB_2: HSAB.2 To_Power_Board.24 | length 874.3
  Top Layer w12: To_Power_Board.24 3300,4850 3375,4850 3500,4725 3875,4725 HSAB.2
NetHSUA_1: HSUA.1 LSUB.1 U23.4 | length 1344.8
  Top Layer w19: LSUB.1 3085,4415 3780,4415 v1(3800,4395)
  Top Layer w23: U23.4 v1(3800,4125)
  Top Layer w60: HSUA.1 LSUB.1
  Bottom Layer w25: v1(3800,4125) v1(3800,4395)
NetHSUA_2: HSUA.2 To_Power_Board.18 | length 432.8
  Top Layer w12: HSUA.2 2850,4600 3000,4750 3000,4850 To_Power_Board.18
NetHSUB_1: HSUB.1 LSUA.1 U23.7 | length 1716.2
  Top Layer w12: LSUA.1 2650,4550 3150,4550 HSUB.1 3255,4445 3900,4445 v1(3950,4395)
  Top Layer w23: U23.7@3950,4113.7 v1(3950,4125)
  Bottom Layer w25: v1(3950,4125) v1(3950,4395)
NetHSUB_2: HSUB.2 To_Power_Board.20 | length 362.1
  Top Layer w12: To_Power_Board.20 3100,4850 3100,4700 HSUB.2
NetIOH1_3: IOH1.3 To_Power_Board.9 | length 1837.6
  Top Layer w12: v1(2790,3625) 3035,3625 IOH1.3
  Bottom Layer w12: To_Power_Board.9 2665,4685 2665,4250 2790,4125 v1(2790,3625)
NetIOH1_5: IOH1.5 To_Power_Board.10 | length 1755.2
  Bottom Layer w12: To_Power_Board.10 2600,4850 2675,4850 2700,4825 2700,4720 2715,4705 2715,4280 2850,4145 2850,3610 IOH1.5
NetIOH1_6: IOH1.6 To_Power_Board.11 | length 1528.4
  Bottom Layer w12: To_Power_Board.11 2650,4735 2690,4695 2690,4265 2825,4130 2825,3600 2960,3465 IOH1.6
NetIOL1_1: IOL1.1 R22.1 | length 2238.3
  Top Layer w12: R22.1 2630,2870 3965,2870 4275,3180 4275,3355 IOL1.1
NetIOL1_3: IOL1.3 R13.1 U33.13 | length 1567
  Top Layer w11.4: v1(3770,2955) 3800,2925 3950,2925 4120,3095 IOL1.3
  Top Layer w23: v1(3770,2955) U33.13
  Top Layer w45: R13.1 v1(3725,2245)
  Bottom Layer w23: v1(3725,2245) 3770,2290 v1(3770,2955)
NetIOL1_5: IOL1.5 R6.1 To_Power_Board.15 | length 2158.5
  Top Layer w12: v1(3200,3650) 3670,3650 IOL1.5
  Top Layer w45: R6.1 v1(2955,4035)
  Bottom Layer w12: To_Power_Board.15 2925,4725 2925,4065 v1(2955,4035) 3200,3790 v1(3200,3650)
NetIOL1_6: IOL1.6 R8.1 U33.1 | length 928.4
  Top Layer w12: v1(3460,3600) 3620,3600 IOL1.6
  Top Layer w23: U33.1 IOL1.6
  Top Layer w45: v1(3460,3845) R8.1
  Bottom Layer w23: v1(3460,3600) v1(3460,3845)
NetIOL1_7: IOL1.7 R54.1 U33.3 | length 2384
  Top Layer w12: v1(2760,3665) 3050,3665 3165,3550 3570,3550 IOL1.7
  Top Layer w23: U33.3 IOL1.7
  Top Layer w25: R54.1 2315,4375 v1(2500,4375)
  Bottom Layer w12: v1(2500,4375) 2760,4115 v1(2760,3665)
NetJ1_3: J1.3 To_Power_Board.26 | length 1915.8
  Top Layer w12: J1.3 2050,4800 2100,4850 2280,4850 2300,4830 2300,4765 2325,4740 2475,4740 2500,4765 2500,4935 2520,4955 3295,4955 To_Power_Board.26
NetL80_1: L80.1 U80.8 | length 108
  Top Layer w25: L80.1 U80.8
NetLSAA_2: LSAA.2 To_Power_Board.21 | length 365.1
  Top Layer w12: To_Power_Board.21 3150,4745 3295,4600 LSAA.2
NetLSAB_2: LSAB.2 To_Power_Board.23 | length 632.8
  Top Layer w12: To_Power_Board.23 3350,4700 3700,4700 LSAB.2
NetLSUA_2: LSUA.2 To_Power_Board.17 | length 432.8
  Top Layer w12: LSUA.2 2675,4675 2825,4675 To_Power_Board.17
NetLSUB_2: LSUB.2 To_Power_Board.19 | length 220.7
  Top Layer w12: LSUB.2 3050,4650 To_Power_Board.19
NetPower_1: Power.1 R86.2 | length 315
  Top Layer w45: Power.1 R86.2
NetQ31_3: Q31.3 R35.2 R70.2 | length 214.5
  Top Layer w45: Q31.3 1395,3801.18 R70.2 1425,3890 R35.2
NetQ32_3: Q32.3 R51.2 | length 78.8
  Top Layer w45: Q32.3 R51.2
NetQ33_1: Q33.1 R52.2 R53.1 | length 209.9
  Top Layer w23: Q33.1 1737.4,4672.4 R52.2
  Top Layer w45: R52.2 R53.1
NetQ33_3: Q33.3 R30.1 | length 321.1
  Top Layer w23: Q33.3 1738.82,4435 R30.1
NetQ34_1: Q34.1 R54.2 R55.1 | length 192
  Top Layer w23: R55.1@2132.4,4547.6 R55.1
  Top Layer w45: Q34.1 R55.1@2132.4,4547.6 ; R55.1 R54.2
NetQ34_3: Q34.3 R53.2 | length 98.8
  Top Layer w50: R53.2 Q34.3
NetR9_2: R9.2 R63.2 To_Power_Board.3 | length 6124.5
  Top Layer w12: 2185,2480 v1(3875,2480)
  Top Layer w45: v1(2072.56,2480) R63.2 2185,2480 ; R9.2 v1(4290,1770)
  Bottom Layer w12: v1(2072.56,2480) 1850,2480 1285,3045 1285,3395 1235,3445 1235,4045 1265,4075 1510,4075 2155,4720 2215,4720 2250,4755 To_Power_Board.3
  Bottom Layer w25: v1(3875,2480) 3890,2480 4240,2130 4240,1820 v1(4290,1770)
NetR10_2: R10.2 R62.2 To_Power_Board.4 | length 6235.2
  Top Layer w12: v1(1995,2450) 2030,2450 2050,2430 2215,2430 2240,2455 3860,2455 v1(3875,2440)
  Top Layer w45: v1(1995,2450) R62.2 ; R10.2 v1(4200,1770)
  Bottom Layer w12: v1(1995,2450) 1845,2450 1260,3035 1260,3385 1210,3435 1210,4055 1255,4100 1500,4100 2145,4745 2185,4745 2200,4760 2200,4850 To_Power_Board.4
  Bottom Layer w25: v1(3875,2440) 4200,2115 v1(4200,1770)
NetR12_1: R12.1 U33.12 | length 849.9
  Top Layer w23: v1(3720,2955) U33.12
  Top Layer w45: R12.1 v1(3625,2245)
  Bottom Layer w23: v1(3625,2245) 3720,2340 v1(3720,2955)
NetR19_2: R19.2 R36.2 R37.2 To_Power_Board.7 | length 3859.1
  Top Layer w12: R19.2 1855,3365 1870,3380 1870,3450 1885,3465 1965,3465 1975,3475 1975,3565 R37.2@1925,3615 ; v1(2020,4870) 2105,4955 2380,4955 2400,4935 2400,4850 To_Power_Board.7
  Top Layer w25: v1(1230,3325) 1430,3325 1455,3300 1560,3300 R19.2
  Top Layer w45: R19.2 1625,3420 1715,3510 R36.2
  Bottom Layer w12: v1(1230,3325) 1230,3380 1185,3425 1185,4065 1245,4125 1490,4125 2000,4635 2000,4850 v1(2020,4870)
NetR32_1: R32.1 U30.2 | length 217.3
  Top Layer w23: R32.1 1885,4180 1885,4150 1910,4125 U30.2
NetR40_1: R40.1 U30.11 | length 1645
  Top Layer w12: U30.11 2365,3925 2390,3950 2570,3950 2795,3725 3315,3725 3365,3675 3680,3675 R40.1
NetR42_1: R42.1 U30.12 | length 2483.5
  Top Layer w12: U30.12 2585,3975 2810,3750 3325,3750 3375,3700 3625,3700 3700,3775 4175,3775 4280,3880 R42.1
NetR44_1: R44.1 U30.13 | length 1338.9
  Top Layer w12: U30.13 2575,4025 2825,3775 3430,3775 R44.1
NetR46_1: R46.1 U30.14 | length 2097
  Top Layer w12: U30.14 2565,4075 2840,3800 4100,3800 R46.1
NetR61_1: R61.1 R66.2 U48.1 | length 319.6
  Top Layer w23: R61.1 1975,2740 U48.1
  Top Layer w45: R66.2 1770,2735 1835,2670 R61.1
NetR61_2: R61.2 R62.1 U48.2 | length 211.1
  Top Layer w23: R61.2 2025,2700 U48.2
  Top Layer w45: R62.1 R61.2
NetR63_1: R63.1 R64.2 U48.3 | length 207
  Top Layer w23: U48.3 2075,2690 R64.2
  Top Layer w45: R63.1 R64.2
NetR80_1: R80.1 U80.5 | length 100.5
  Top Layer w25: R80.1 1201.3,1793.7 U80.5
NetR83_2: R83.2 R84.1 R85.1 U80.4 | length 634.4
  Top Layer w23: R85.1@1201.3,2006.3 U80.4
  Top Layer w45: R84.1 v1(1150,2000) R85.1 ; R83.2 v1(1200,1620)
  Bottom Layer w25: v1(1150,2000) 1150,1670 v1(1200,1620)
NetU23_15: U23.15 U24.15 U33.4 | length 2016.1
  Top Layer w23: U24.15 3150,4355 3165,4370 v1(3375,4370) 3680,4370 3700,4350 U23.15 ; U33.4 v1(3670,3280)
  Bottom Layer w23: v1(3375,4370) 3375,4055 3520,3910 3520,3325 3565,3280 v1(3670,3280)
VDD: 
pads on no net: AD1.5 AD1.6 H16.1 H17.1 H18.1 H19.1 IOH1.1 IOH1.2 IOH1.8 IOL1.4 IOL1.8 POWER_MCU.1 POWER_MCU.3 POWER_MCU.5 POWER_MCU.8 To_Power_Board.13 U24.5 U24.6 U24.7 U24.9 U24.10 U24.11 U24.12 U24.13 U24.14 U33.5 U33.6 U33.8 U33.9 U33.10 U33.11 U48.5 U48.6 U48.7 U48.8 U48.9 U48.10 U80.7
copper on no net: | length 8.9
  Top Layer w23: 1195,2000 1201.3,2006.3

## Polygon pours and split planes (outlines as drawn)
GND on Bottom Layer "Bottom Layer-No Net 1" (solid, pour order 0): 1815,4350 2320,4350 2575,4095 2575,3595 2405,3425 2405,2705 2210,2510 1850,2510 1305,3055 1305,3405 1255,3455 1255,4035 1275,4055 1520,4055
GND on Bottom Layer "Bottom Layer-No Net 1" (solid, pour order 2): 1915,1465 1800,1350 1800,1285 1390,1285 1275,1400 1125,1400 1050,1475 1050,2200 1125,2275 1500,2275 1660,2115 1660,1790 1675,1775 1915,1775
GND on Bottom Layer "Bottom Layer-No Net 1" (solid, pour order 8): 3367.83,4957.17 3400,4925 3400,4870 3380,4850 3325,4850 3305,4830 3305,4780 3455,4630 3455,4090 3545,4000 3695,4000 3710,3985 3710,3940 3665,3895 3665,3660 3775,3550 4200,3550 4375,3725 4375,4400 3775,5000 3410,5000
GND on Top Layer "Bottom Layer-No Net 1" (solid, pour order 10): 2650,3225 2600,3175 2600,3055 2730,2925 3925,2925 4100,3100 4100,3300 4075,3325 3425,3325 3325,3225
GND on Top Layer "Bottom Layer-No Net 1" (solid, pour order 6): 2900,4350 2950,4400 4325,4400 4375,4350 4375,3875 4320,3820 2980,3820 2900,3900

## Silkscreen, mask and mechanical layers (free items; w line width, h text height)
Top Overlay:
  lines w10: 2320,3220 2345,3195 ; 2345,3345 2345,3195 ; 2370,3220 2345,3195 ; 2400,3260 2400,3300 ; 2435,3300 2400,3300 ; 2510,3190 2400,3300 ; 2310,3345 2480,3345 2480,3645 2310,3645 2310,3345 ; 2540,2480 2540,3280 2885,3280 2905,3280 2905,2480 2540,2480
  text "SEC China" at 2450,2125 h120
  text "6.6KW CLLC Bridge Board" at 1750,2000 h120
  text "Ver. 3.1 2022.01. 10" at 1750,1875 h120
Mechanical 1:
  the board outline again, w10
Mechanical 2:
  region: 4500,1400 4500,3500 3100,3500 3100,3800 1800,3800 1800,1400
